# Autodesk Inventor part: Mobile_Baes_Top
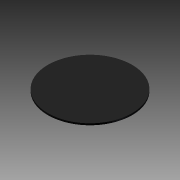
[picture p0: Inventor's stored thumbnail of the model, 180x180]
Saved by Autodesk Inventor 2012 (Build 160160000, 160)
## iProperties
Created: 2014-02
Part Number: Mobile_Baes_Top
Material: Default
Document SubType Name: Modeling
Designer: Aser
Density: 1 g/cm^3
Author: Aser
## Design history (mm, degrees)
sketch "Sketch1"
  geometry: C1 r 250 at (0, 0); 1 further point
  constraints: 1 centre point, 1 coincident
  dimensions: "d0" = 500 dimension on point (0, 0) C1.centre C1; "d0" = 500 diameter of C1
extrude "Extrusion1" new body sketch "Sketch1" distance "d1" = 10; taper "d2" = 0 deg
body "Solid1"
